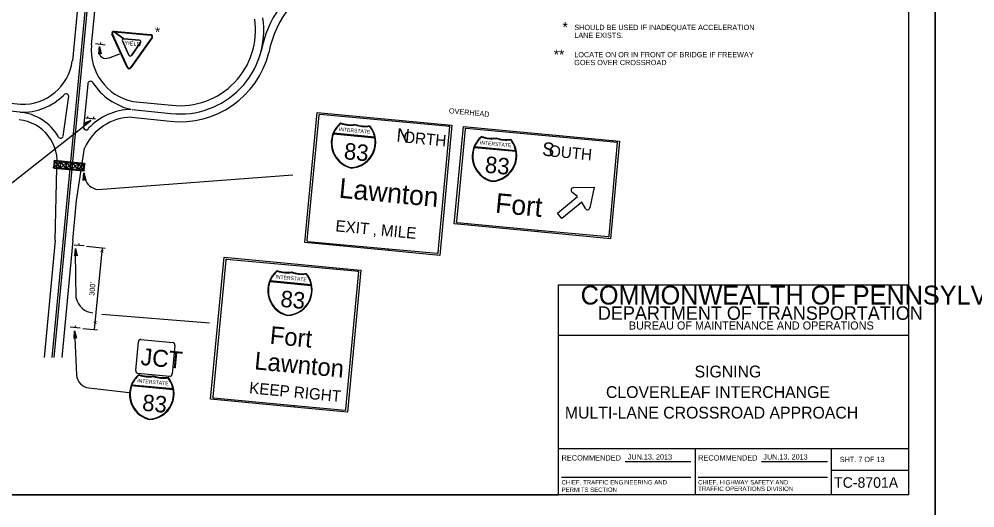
# Model space of a CAD drawing. Extents: x 644898 to 648326, y 298294 to 300670.
# Drawn here: x 646898 to 647444, y 299490 to 299769 of the extents above; entities that cross this region are included whole.
import ezdxf

# ---------------------------------------------------------------- set-up
doc = ezdxf.new("R2010")
doc.units = 0
for name, color, linetype in [('1', 7, 'Continuous'), ('2', 7, 'Continuous'), ('XCS-GRID-MIN', 7, 'Continuous')]:
    doc.layers.add(name, color=color, linetype=linetype)

msp = doc.modelspace()

# ---------------------------------------------------------------- linework, layer by layer
at = {"layer": '1'}
for p, q in [((647406.32, 299497.49), (647406.32, 300061.49)), ((647206.32, 299497.49), (647206.32, 299617.49)), ((647206.32, 299617.49), (647406.32, 299617.49)), ((647406.32, 299588.49), (647206.32, 299588.49)), ((647206.32, 299523.87), (647406.32, 299523.87)), ((647284.32, 299523.87), (647284.32, 299497.49)), ((647362.2, 299497.49), (647362.2, 299523.87)), ((647244.26, 299516.44), (647281.88, 299516.44)), ((647322.26, 299516.44), (647359.88, 299516.44)), ((647362.2, 299511.49), (647406.32, 299511.49)), ((647208.01, 299507.54), (647281.88, 299507.54)), ((647286.01, 299507.54), (647359.88, 299507.54)), ((647406.32, 299497.49), (646620.32, 299497.49)), ((646620.32, 299497.49), (647206.32, 299497.49))]:
    msp.add_line(p, q, dxfattribs=at)
at = {"layer": '2'}
for p, q in [((646961.82, 300046.87), (646916.95, 299575.99)), ((646962.95, 300046.87), (646918.07, 299575.99)), ((646949.82, 299862.24), (646939.45, 299754.37)), ((646938.95, 299854.24), (646928.7, 299745.49)), ((646952.45, 299762.37), (646973.32, 299760.49)), ((646952.45, 299762.12), (646973.32, 299760.12)), ((646958.07, 299757.99), (646952.45, 299762.12)), ((646952.45, 299762.12), (646973.32, 299760.12)), ((646952.45, 299762.12), (646958.07, 299757.99)), ((646939.95, 299759.37), (646939.95, 299759.37)), ((646959.95, 299741.74), (646951.2, 299760.74)), ((646960.32, 299741.74), (646951.57, 299760.87)), ((646960.32, 299741.74), (646951.57, 299760.87)), ((646960.95, 299748.74), (646957.2, 299756.87)), ((646957.2, 299756.87), (646960.95, 299748.74)), ((646958.07, 299757.99), (646958.07, 299758.12)), ((646958.07, 299757.99), (646966.95, 299757.24)), ((646966.95, 299757.24), (646958.07, 299757.99)), ((646973.95, 299758.74), (646961.82, 299741.74)), ((646973.95, 299758.74), (646961.82, 299741.74)), ((646974.2, 299758.62), (646962.07, 299741.49)), ((646947.45, 299754.49), (646941.82, 299755.12)), ((646944.7, 299754.87), (646944.82, 299755.99)), ((646962.2, 299754.24), (646962.2, 299754.24)), ((646967.57, 299755.87), (646962.45, 299748.62)), ((646962.45, 299748.62), (646967.57, 299755.87)), ((646937.45, 299732.24), (646935.07, 299707.49)), ((646923.45, 299702.37), (646926.7, 299725.37)), ((646898.7, 299716.12), (646869.7, 299718.99)), ((646899.07, 299720.62), (646870.07, 299723.49)), ((646963.07, 299722.24), (646985.45, 299720.12)), ((646937.45, 299712.62), (646937.45, 299713.74)), ((646940.82, 299712.37), (646940.95, 299713.49)), ((646962.32, 299713.24), (646984.41, 299710.95)), ((646962.7, 299717.74), (646984.9, 299715.38)), ((647061.37, 299641.57), (647068.52, 299715.99)), ((647069.4, 299714.36), (647062.62, 299642.95)), ((647068.52, 299715.99), (647145.36, 299708.66)), ((646874.72, 299660.52), (646937.82, 299710.3)), ((646941.82, 299712.24), (646936.32, 299712.74)), ((647081.94, 299709.58), (647081.94, 299709.58)), ((647090.19, 299708.83), (647090.19, 299708.83)), ((647098.31, 299708.08), (647098.31, 299708.08)), ((647137.55, 299635.9), (647144.17, 299708)), ((647145.36, 299708.66), (647138.4, 299634.24)), ((647146.69, 299652.27), (647152.07, 299708.02)), ((647152.07, 299708.01), (647241.19, 299699.52)), ((647077.81, 299703.71), (647101.31, 299701.46)), ((647101.31, 299701.83), (647077.94, 299704.08)), ((647152.94, 299706.39), (647147.94, 299653.64)), ((647162.44, 299701.89), (647162.44, 299701.89)), ((647170.69, 299701.14), (647170.69, 299701.14)), ((647178.82, 299700.39), (647178.82, 299700.39)), ((647235.19, 299645.39), (647240.01, 299698.86)), ((647241.19, 299699.52), (647235.94, 299643.77)), ((646931.07, 299665.62), (646935.57, 299695.49)), ((647158.32, 299696.02), (647181.82, 299693.77)), ((647181.82, 299694.14), (647158.44, 299696.39)), ((646918.18, 299687.98), (646917.93, 299684.73)), ((646918.68, 299687.98), (646918.3, 299684.73)), ((646918.3, 299684.73), (646921.93, 299687.73)), ((646935.43, 299686.73), (646918.68, 299688.48)), ((646918.68, 299687.98), (646921.68, 299684.23)), ((646921.68, 299684.23), (646925.3, 299687.35)), ((646921.93, 299687.73), (646924.93, 299683.98)), ((646924.93, 299683.98), (646928.68, 299686.98)), ((646925.3, 299687.35), (646928.3, 299683.6)), ((646928.3, 299683.6), (646931.93, 299686.73)), ((646928.68, 299686.98), (646931.68, 299683.35)), ((646931.68, 299683.35), (646935.3, 299686.35)), ((646931.93, 299686.73), (646934.93, 299682.98)), ((646931.93, 299685.98), (646931.93, 299685.98)), ((646934.93, 299682.98), (646935.3, 299686.35)), ((646935.43, 299682.98), (646935.68, 299686.35)), ((646918.18, 299684.23), (646934.93, 299682.6)), ((646918.82, 299642.87), (646919.7, 299684.24)), ((646926.8, 299685.48), (646926.8, 299685.48)), ((646926.8, 299685.48), (646926.8, 299685.48)), ((646935.16, 299681.4), (646936.03, 299678.15)), ((646943.08, 299672.02), (647054.54, 299680.34)), ((647217.07, 299667.89), (647213.82, 299670.52)), ((647214.82, 299673.02), (647226.69, 299673.27)), ((647226.69, 299673.27), (647224.19, 299661.52)), ((646928.95, 299642.87), (646931.07, 299665.62)), ((647205.69, 299658.52), (647217.07, 299667.89)), ((647219.57, 299664.77), (647208.19, 299655.39)), ((647221.69, 299661.02), (647219.57, 299664.77)), ((647208.19, 299655.39), (647205.69, 299658.52)), ((647148.32, 299653.02), (647194.59, 299648.73)), ((647194.49, 299647.72), (647146.69, 299652.27)), ((647194.49, 299647.72), (647194.59, 299648.73)), ((647194.59, 299648.73), (647194.49, 299647.72)), ((647235.94, 299643.77), (647194.49, 299647.72)), ((647194.59, 299648.73), (647234.57, 299645.02)), ((646918.82, 299642.87), (646912.45, 299575.99)), ((646928.95, 299642.87), (646922.57, 299575.99)), ((647062.99, 299642.32), (647109.26, 299638.03)), ((646935.27, 299639.67), (646929.65, 299640.17)), ((646932.4, 299639.92), (646932.52, 299641.04)), ((646936.63, 299639.48), (646947.45, 299638.49)), ((646941.32, 299591.87), (646945.82, 299638.62)), ((647109.17, 299637.02), (647061.37, 299641.57)), ((647109.17, 299637.02), (647109.26, 299638.03)), ((647109.26, 299638.03), (647109.17, 299637.02)), ((647138.4, 299634.24), (647109.17, 299637.02)), ((647109.26, 299638.03), (647136.92, 299635.51)), ((646930.77, 299609.76), (646930.32, 299635.79)), ((647007.56, 299552.09), (647015.36, 299633.24)), ((647016.23, 299631.61), (647008.82, 299553.5)), ((647015.36, 299633.23), (647093.37, 299625.79)), ((647093.37, 299625.79), (647085.7, 299544.65)), ((647045.68, 299625.22), (647045.68, 299625.22)), ((647053.93, 299624.47), (647053.93, 299624.47)), ((647062.05, 299623.72), (647062.05, 299623.72)), ((647084.89, 299546.33), (647092.18, 299625.13)), ((647041.55, 299619.34), (647065.05, 299617.09)), ((647065.05, 299617.47), (647041.68, 299619.72)), ((646945.41, 299600.68), (647006.94, 299595.76)), ((646933.07, 299592.74), (646927.45, 299593.24)), ((646930.2, 299592.99), (646930.32, 299594.12)), ((646929.82, 299591.12), (646930.99, 299565.97)), ((646934.57, 299592.49), (646942.95, 299591.74)), ((646964.87, 299568.6), (646966.37, 299584.85)), ((646967.62, 299586.22), (646986.12, 299584.47)), ((646987.12, 299582.85), (646985.62, 299566.6)), ((646984.24, 299565.1), (646965.87, 299566.85)), ((646966.74, 299565.85), (646966.74, 299565.85)), ((646986.12, 299558.1), (646962.74, 299560.22)), ((646974.87, 299565.1), (646974.87, 299565.1)), ((646983.12, 299564.35), (646983.12, 299564.35)), ((646937.99, 299558.6), (646960.99, 299555.97)), ((646962.49, 299559.97), (646986.12, 299557.72)), ((647055.36, 299547.54), (647007.56, 299552.09)), ((647009.19, 299552.84), (647055.46, 299548.55)), ((647055.36, 299547.54), (647055.46, 299548.55)), ((647055.46, 299548.55), (647055.36, 299547.54)), ((647085.7, 299544.65), (647055.36, 299547.54)), ((647055.46, 299548.55), (647084.36, 299545.91))]:
    msp.add_line(p, q, dxfattribs=at)
for points in [[(646943.82, 299749.62), (646944.2, 299749.87), (646944.07, 299753.62), (646943.82, 299749.62), (646943.7, 299749.37), (646944.07, 299753.62), (646944.57, 299749.87), (646944.95, 299749.74), (646944.07, 299753.62), (646945.07, 299749.49), (646944.95, 299749.74)], [(647144.27, 299707.99), (647069.9, 299714.74)], [(646935.36, 299709.82), (646935.56, 299709.63), (646939.19, 299711.47), (646935.36, 299709.82), (646935.11, 299709.89), (646939.19, 299711.47), (646935.82, 299709.17), (646935.88, 299708.89), (646939.19, 299711.47), (646935.78, 299708.53), (646935.88, 299708.89)], [(647240.01, 299698.86), (647153.44, 299706.77)], [(646935.03, 299677.39), (646935.29, 299677.48), (646935.16, 299681.4), (646935.03, 299677.39), (646934.87, 299677.16), (646935.16, 299681.4), (646935.8, 299677.54), (646936.03, 299677.39), (646935.16, 299681.4), (646936.27, 299677.23), (646936.03, 299677.39)], [(646930.11, 299634.24), (646930.38, 299634.33), (646930.37, 299638.25), (646930.11, 299634.24), (646929.95, 299634.01), (646930.37, 299638.25), (646930.89, 299634.37), (646931.12, 299634.21), (646930.37, 299638.25), (646931.35, 299634.05), (646931.12, 299634.21)], [(647092.17, 299625.13), (647016.73, 299631.99)], [(646929.93, 299586.99), (646930.16, 299587.26), (646929.82, 299591.12), (646929.93, 299586.99), (646929.69, 299586.73), (646929.82, 299591.12), (646930.54, 299587.28), (646930.79, 299587.17), (646929.82, 299591.12), (646931.06, 299586.93), (646930.79, 299587.17)]]:
    msp.add_lwpolyline(points, dxfattribs=at)
for points in [[(646921.68, 299684.23), (646918.3, 299684.73), (646918.68, 299687.98), (646921.93, 299687.73)], [(646924.93, 299683.98), (646921.68, 299684.23), (646921.93, 299687.73), (646925.3, 299687.35)], [(646928.3, 299683.6), (646924.93, 299683.98), (646925.3, 299687.35), (646928.68, 299686.98)], [(646931.68, 299683.35), (646928.3, 299683.6), (646928.68, 299686.98), (646931.93, 299686.73)], [(646934.93, 299682.98), (646931.68, 299683.35), (646931.93, 299686.73), (646935.3, 299686.35)]]:
    msp.add_lwpolyline(points, close=True, dxfattribs=at)
for centre in [(646918.4, 299688.22), (646935.54, 299686.59), (646918.04, 299684.45), (646935.18, 299682.82)]:
    msp.add_circle(centre, 0.3, dxfattribs=at)
for centre, radius, start, end in [((647099.43, 299738.97), 64.14, 120.4682, 169.2063), ((647099.43, 299738.97), 59.66, 112.7883, 169.2063), ((646990.11, 299762.94), 47.84, 263.7511, 8.5263), ((646990.11, 299762.94), 43.11, 263.7511, 8.5263), ((646952.34, 299761.26), 1.18, 84.5662, 204.5663), ((646952.34, 299761.26), 0.871, 84.5662, 204.5663), ((646952.34, 299761.26), 0.871, 84.5662, 204.5663), ((646958.02, 299757.22), 0.871, 84.5662, 204.5662), ((646958.02, 299757.22), 0.871, 84.5662, 204.5662), ((646966.9, 299756.37), 0.871, 324.5663, 84.5662), ((646966.9, 299756.37), 0.871, 324.5663, 84.5662), ((646973.24, 299759.27), 0.871, 324.5662, 84.5662), ((646973.24, 299759.27), 0.871, 324.5662, 84.5662), ((646973.24, 299759.27), 1.18, 324.5662, 84.5662), ((646969.48, 299751.61), 30.09, 174.798, 257.7913), ((646961.73, 299749.1), 0.871, 204.5663, 324.5662), ((646961.73, 299749.1), 0.871, 204.5663, 324.5662), ((646990.11, 299762.94), 52.3, 263.7511, 345.8438), ((646900.18, 299749.3), 28.67, 267.7875, 352.2254), ((646961.07, 299742.16), 1.18, 204.5663, 324.5662), ((646961.07, 299742.16), 0.871, 204.5663, 324.5662), ((646961.07, 299742.16), 0.871, 204.5663, 324.5662), ((646938.98, 299732.23), 1.58, 26.5185, 181.1633), ((646969.48, 299751.61), 34.57, 212.5883, 257.7913), ((646900.18, 299749.3), 33.15, 267.7875, 315.0975), ((646925, 299724.9), 1.67, 14.023, 143.0689), ((646895.93, 299687.83), 28.5, 29.9854, 84.5024), ((646962.98, 299683.19), 30.1, 91.3442, 155.7409), ((646962.98, 299683.2), 34.57, 91.3421, 136.5451), ((647069.84, 299714.29), 0.528, 84.2894, 175.6013), ((646895.93, 299687.83), 24.02, 351.1999, 84.5024), ((646936.48, 299707.43), 1.47, 163.8304, 341.9987), ((647091.26, 299698.58), 14.78, 129.5662, 256.4361), ((647091.26, 299698.58), 14.47, 130.2586, 157.7735), ((647087.57, 299725.97), 16.98, 250.3162, 278.8163), ((647087.57, 299725.97), 17.29, 250.9067, 278.5552), ((647087.1, 299698.98), 14.78, 272.6963, 39.5662), ((647095.89, 299725.18), 17.29, 250.5773, 278.2258), ((647095.89, 299725.18), 16.98, 250.3162, 278.8163), ((647087.1, 299698.98), 14.47, 11.359, 38.8739), ((646921.97, 299702.8), 1.53, 208.2474, 339.8234), ((647091.26, 299698.58), 14.47, 159.0531, 256.4361), ((647153.38, 299706.32), 0.528, 84.2894, 175.6013), ((647171.77, 299690.89), 14.78, 129.5662, 256.4361), ((647171.77, 299690.89), 14.47, 130.2586, 157.7735), ((647168.07, 299718.28), 16.98, 250.3162, 278.8163), ((647168.07, 299718.28), 17.29, 250.9067, 278.5552), ((647087.1, 299698.98), 14.47, 272.6964, 10.0794), ((647167.6, 299691.29), 14.78, 272.6963, 39.5662), ((647176.4, 299717.49), 17.29, 250.5773, 278.2258), ((647176.4, 299717.49), 16.98, 250.3162, 278.8163), ((647167.6, 299691.29), 14.47, 11.359, 38.8739), ((647239.49, 299698.22), 0.528, 354.144, 84.5077), ((647171.77, 299690.89), 14.47, 159.0531, 256.4361), ((647167.6, 299691.29), 14.47, 272.6964, 10.0794), ((646943.77, 299679.99), 8, 192.9946, 265.0303), ((647214.84, 299671.59), 1.4, 89.4252, 230.0907), ((647222.84, 299661.79), 1.4, 207.8136, 351.7203), ((647148.39, 299653.58), 0.528, 174.0939, 265.2364), ((647063.07, 299642.88), 0.528, 174.0939, 265.2364), ((647234.64, 299645.46), 0.528, 264.8056, 354.9575), ((647016.67, 299631.54), 0.528, 84.2894, 175.6013), ((647055, 299614.22), 14.78, 129.5662, 256.4361), ((647051.31, 299641.61), 16.98, 250.3162, 278.8163), ((647055, 299614.22), 14.47, 130.2586, 157.7735), ((647051.31, 299641.61), 17.29, 250.9067, 278.5552), ((647050.84, 299614.62), 14.78, 272.6963, 39.5662), ((647059.63, 299640.81), 17.29, 250.5773, 278.2258), ((647059.63, 299640.81), 16.98, 250.3162, 278.8163), ((647050.84, 299614.62), 14.47, 11.359, 38.8739), ((647055, 299614.22), 14.47, 159.0531, 256.4361), ((647050.84, 299614.62), 14.47, 272.6964, 10.0794), ((646941.24, 299612.18), 10.75, 192.9946, 264.9668), ((646938.95, 299566.54), 8, 184.4846, 263.4181), ((646976.07, 299554.81), 14.78, 129.5662, 256.4361), ((646976.07, 299554.81), 14.47, 130.2586, 157.7735), ((646972.38, 299582.2), 16.98, 250.3162, 278.8163), ((646972.38, 299582.2), 17.29, 250.9067, 278.5552), ((646971.91, 299555.21), 14.78, 272.6963, 39.5662), ((646980.7, 299581.4), 17.29, 250.5773, 278.2258), ((646980.7, 299581.4), 16.98, 250.3162, 278.8163), ((646971.91, 299555.21), 14.47, 11.359, 38.8739), ((646976.07, 299554.81), 14.47, 159.0531, 256.4361), ((646971.91, 299555.21), 14.47, 272.6964, 10.0794)]:
    msp.add_arc(centre, radius, start, end, dxfattribs=at)
for centre, major_axis, ratio, start_param, end_param in [((647143.65, 299707.35), (0.642, 0), 0.836215, 6.180979, 7.758122), ((647136.99, 299635.96), (0, -0.54), 0.976877, 6.192525, 7.765974), ((647091.67, 299624.5), (0, 0.527), 0.978402, 4.610182, 6.187326), ((646967.52, 299584.71), (-0.15, -1.55), 0.769266, 3.141593, 4.712389), ((646985.95, 299582.96), (0.15, 1.55), 0.769266, 4.712389, 6.283185), ((646965.97, 299568.48), (-0.15, -1.55), 0.769266, 4.712389, 6.283185), ((646984.41, 299566.72), (0.15, 1.55), 0.769266, 3.141593, 4.712389), ((647009.26, 299553.43), (0, 0.555), 0.945708, 1.467715, 3.058451), ((647084.42, 299546.39), (0, -0.57), 0.768686, 6.192525, 7.765974)]:
    msp.add_ellipse(centre, major_axis=major_axis, ratio=ratio, start_param=start_param, end_param=end_param, dxfattribs=at)
msp.add_spline([(646955.57, 299749.37), (646950.57, 299747.37), (646946.32, 299746.87), (646944.45, 299748.62), (646944.07, 299753.62)], degree=3, dxfattribs=at)
at = {"layer": 'XCS-GRID-MIN'}
for points in [[(646580.32, 300076.49), (647421.32, 300076.49), (647421.32, 299482.49), (646580.32, 299482.49)], [(647421.32, 300076.49), (648262.32, 300076.49), (648262.32, 299482.49), (647421.32, 299482.49)]]:
    msp.add_lwpolyline(points, close=True, dxfattribs=at)

# ---------------------------------------------------------------- texts
at = {"layer": '1'}
for s, height, p in [('COMMONWEALTH OF PENNSYLVANIA', 10.7828, (647218.92, 299606.23)), ('DEPARTMENT OF TRANSPORTATION', 7.6837, (647228.78, 299597.48)), ('BUREAU OF MAINTENANCE AND OPERATIONS', 4.6253, (647246.42, 299591.91)), ('SIGNING', 6.75, (647283.97, 299564.56)), ('CLOVERLEAF INTERCHANGE', 6.75, (647233.38, 299552.81)), ('MULTI-LANE CROSSROAD APPROACH', 6.75, (647209.91, 299541.06)), ('RECOMMENDED', 3.048, (647208.01, 299517.07)), ('RECOMMENDED', 3.048, (647286.01, 299517.07)), ('SHT. 7 OF 13', 3, (647366.91, 299516.18)), ('CHIEF, TRAFFIC ENGINEERING AND', 2.5, (647208.01, 299503.38)), ('CHIEF, HIGHWAY SAFETY AND', 2.5, (647286.01, 299503.38)), ('TC-8701A', 6, (647363.69, 299501.49)), ('PERMITS SECTION', 2.5, (647208.01, 299499.13)), ('TRAFFIC OPERATIONS DIVISION', 2.5, (647286.01, 299499.68))]:
    msp.add_text(s, height=height, dxfattribs=at).set_placement(p)
at = {"layer": '2'}
for s, height, p in [('*', 5.85, (647208.55, 299761.78)), ('*', 5.85, (646975.79, 299759.02)), ('SHOULD BE USED IF INADEQUATE ACCELERATION', 3, (647215.31, 299763.08)), ('LANE EXISTS.', 3, (647215.31, 299758.58)), ('**', 5.853, (647203.51, 299746.08)), ('GOES OVER CROSSROAD', 3, (647215.27, 299743.02)), ('LOCATE ON OR IN FRONT OF BRIDGE IF FREEWAY ', 3, (647215.27, 299747.52)), ('JUN.13, 2013', 3, (647245.79, 299517.65)), ('JUN.13, 2013', 3, (647323.24, 299517.65))]:
    msp.add_text(s, height=height, dxfattribs=at).set_placement(p)
for s, height, rotation, p in [('YIELD', 2.383, 354.5663, (646958.2, 299754.62)), ('OVERHEAD', 3, 354.5683, (647143.57, 299715.56)), ('INTERSTATE', 2.089, 354.5668, (647080.81, 299705.46)), ('N', 7.75, 354.5817, (647113.48, 299699.34)), ('ORTH', 6.5, 354.5683, (647117.37, 299698.84)), ('83', 9.406, 354.5658, (647083.44, 299689.33)), ('INTERSTATE', 2.089, 354.5668, (647161.32, 299697.77)), ('S', 7.75, 354.5817, (647196.69, 299691.39)), ('OUTH', 6.5, 354.5683, (647200.57, 299690.89)), ('83', 9.406, 354.5658, (647163.94, 299681.64)), ('Lawnton', 11.25, 354.5683, (647080.55, 299667.29)), ('Fort', 11.25, 354.5683, (647169.82, 299658.77)), ('EXIT ‚ MILE', 6.4935, 354.5683, (647078.67, 299648.07)), ('A', 2.09, 84.5681, (646946.57, 299635.49)), ('INTERSTATE', 2.089, 354.5668, (647044.55, 299621.09)), ("300'", 3, 84.5019, (646941.15, 299611.11)), ('83', 9.406, 354.5658, (647047.18, 299604.97)), ('A', 2.09, 84.5681, (646942.7, 299594.87)), ('Fort', 10.125, 354.5701, (647041.08, 299583.8)), ('JCT', 9.706, 354.5666, (646967.37, 299571.72)), ('Lawnton', 10.125, 354.5701, (647032.29, 299569.23)), ('INTERSTATE', 2.089, 354.5668, (646965.62, 299561.72)), ('KEEP RIGHT', 6.493, 354.5683, (647029.39, 299555.49)), ('83', 9.406, 354.5658, (646968.24, 299545.6))]:
    msp.add_text(s, height=height, rotation=rotation, dxfattribs=at).set_placement(p)

doc.saveas('drawing.dxf')
